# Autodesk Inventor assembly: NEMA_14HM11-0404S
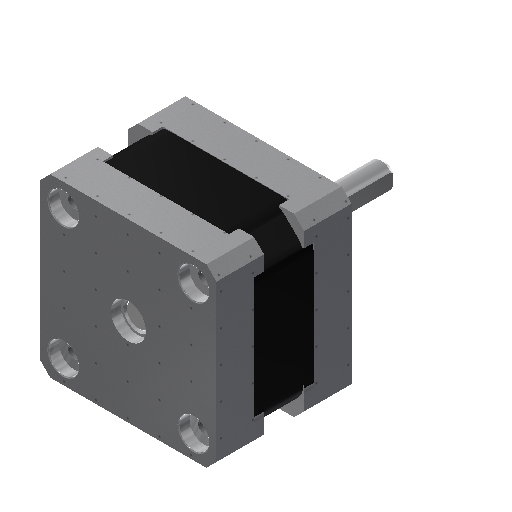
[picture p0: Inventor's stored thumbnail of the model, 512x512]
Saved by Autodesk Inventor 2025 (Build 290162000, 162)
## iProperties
Created: 2019-11
Part Number: NEMA_14HM11-0404S
Material: Générique
Document SubType Name: Assembly
Designer: thoma
Author: thoma
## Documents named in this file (3)
- C:\Users\R5800u\Desktop\nema14\NEMA_14HM11-0404S.iam
- C:\Users\R5800u\Desktop\nema14\NEMA_14HM11-0404S_BODY.ipt
- C:\Users\R5800u\Desktop\nema14\NEMA_14HM11-0404S_SHAFT.ipt
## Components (2 placed, 2 different names)
1. NEMA_14HM11-0404S:1 — Affleurement:2, Placage:2, Placage:3, Affleurement:3
2. NEMA_14HM11-0404S_SHAFT:1 — Affleurement:3
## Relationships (4: Flush 2, Mate 2)
- Affleurement:2 [Flush]: NEMA_14HM11-0404S:1
- Placage:2 [Mate]: NEMA_14HM11-0404S:1
- Placage:3 [Mate]: NEMA_14HM11-0404S:1
- Affleurement:3 [Flush]: NEMA_14HM11-0404S:1 ↔ NEMA_14HM11-0404S_SHAFT:1
